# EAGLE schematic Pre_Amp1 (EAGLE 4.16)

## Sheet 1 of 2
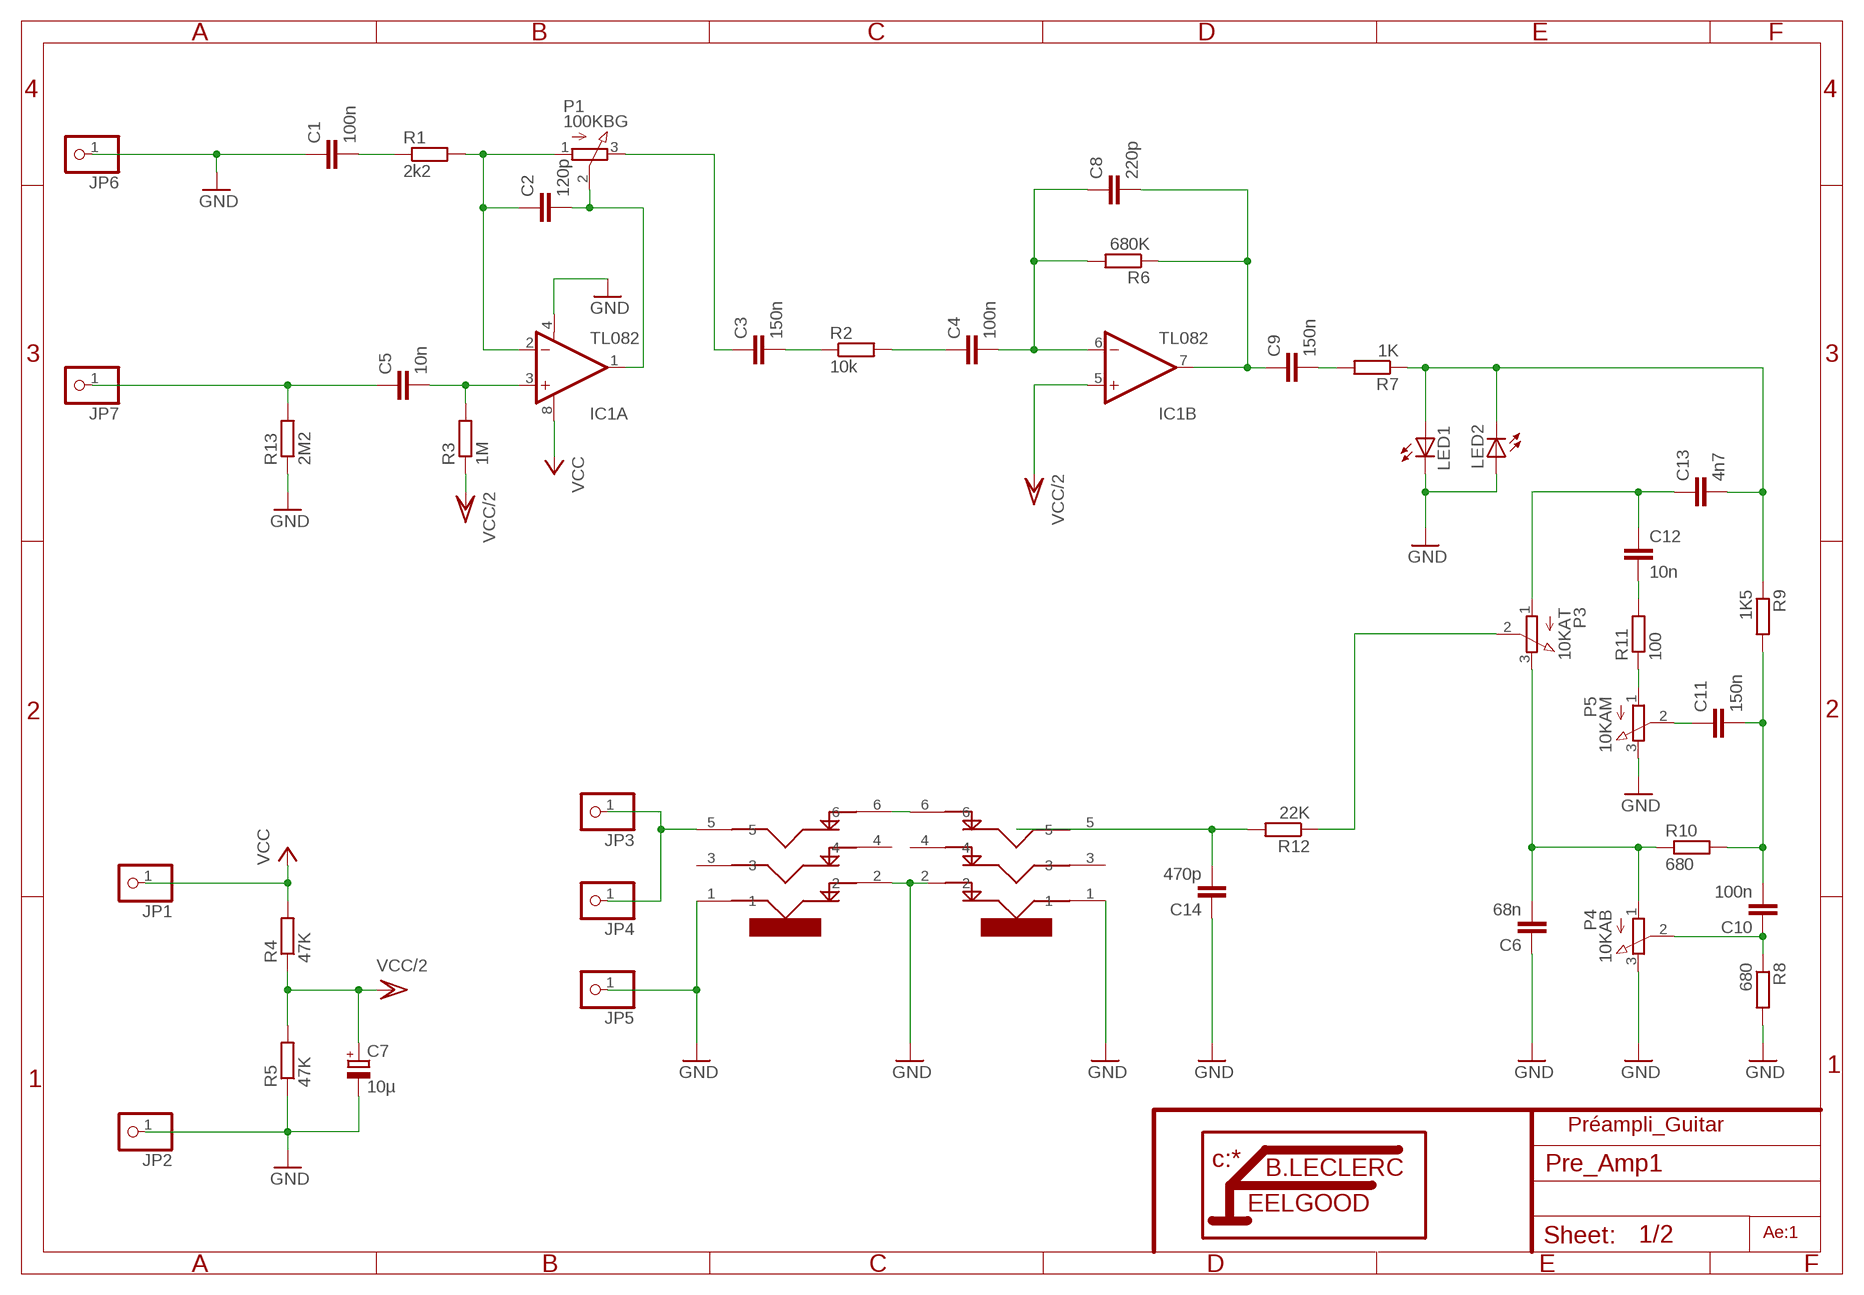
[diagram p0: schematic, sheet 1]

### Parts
C1  100n  C-EU102-043X133  [C102-043X133]
C2  120p  C-EU025-025X050  [C025-025X050]
C3  150n  C-EU102-054X133  [C102-054X133]
C4  100n  C-EU102-054X133  [C102-054X133]
C5  10n  C-EU050-035X075  [C050-035X075]
C6  68n  C-EU050-035X075  [C050-035X075]
C7  10µ  CPOL-EUE2.5-6  [E2,5-6]
C8  220p  C-EU050-030X075  [C050-030X075]
C9  150n  C-EU102-043X133  [C102-043X133]
C10  100n  C-EU102-043X133  [C102-043X133]
C11  150n  C-EU102-043X133  [C102-043X133]
C12  10n  C-EU050-025X075  [C050-025X075]
C13  4n7  C-EU050-025X075  [C050-025X075]
C14  470p  C-EU050-025X075  [C050-025X075]
IC1  TL082  OPA2134P  [DIL08]
J2  Return  JACK635  [JACK635]
J3  Send  JACK635  [JACK635]
JP1  PINHD-1X1  [1X01]
JP2  PINHD-1X1  [1X01]
JP3  PINHD-1X1  [1X01]
JP4  PINHD-1X1  [1X01]
JP5  PINHD-1X1  [1X01]
JP6  PINHD-1X1  [1X01]
JP7  PINHD-1X1  [1X01]
LED1  LED3MM  [LED3MM]
LED2  LED3MM  [LED3MM]
P1  100KBG  STD-EU  [STD-EU]
P3  10KAT  STD-EU  [STD-EU]
P4  10KAB  STD-EU  [STD-EU]
P5  10KAM  STD-EU  [STD-EU]
R1  2k2  R-EU_0207/10  [0207/10]
R2  10k  R-EU_0207/10  [0207/10]
R3  1M  R-EU_0207/10  [0207/10]
R4  47K  R-EU_0207/10  [0207/10]
R5  47K  R-EU_0207/10  [0207/10]
R6  680K  R-EU_0207/10  [0207/10]
R7  1K  R-EU_0207/10  [0207/10]
R8  680  R-EU_0207/10  [0207/10]
R9  1K5  R-EU_0207/10  [0207/10]
R10  680  R-EU_0207/10  [0207/10]
R11  100  R-EU_0207/10  [0207/10]
R12  22K  R-EU_0207/10  [0207/10]
R13  2M2  R-EU_0207/10  [0207/10]

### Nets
GND: C1.1 C6.1 C7.- C14.1 IC1.4(A:V-) J2.1 J2.2 J3.1 J3.2 JP2.1 JP5.1 JP6.1 LED1.K(C) LED2.A P4.3(E) P5.3(E) R5.1 R8.2 R13.1 ; also sheet 2
N$1: C1.2 R1.1
N$2: C2.1 IC1.2(A:-IN) P1.1(A) R1.2
N$3: C2.2 IC1.1(A:OUT) P1.2(S)
N$4: C10.1 P4.2(S) R8.1
N$5: C5.1 JP7.1 R13.2
N$6: C5.2 IC1.3(A:+IN) R3.2
N$7: C6.2 P3.3(E) P4.1(A) R10.1
N$8: C3.1 P1.3(E)
N$9: C3.2 R2.1
N$10: C4.1 R2.2
N$11: C4.2 C8.1 IC1.6(B:-IN) R6.2
N$13: C8.2 C9.1 IC1.7(B:OUT) R6.1
N$14: C9.2 R7.2
N$15: C13.2 LED1.A LED2.K(C) R7.1 R9.1
N$16: P3.2(S) R12.1
N$17: C12.1 C13.1 P3.1(A)
N$18: C12.2 R11.2
N$19: P5.1(A) R11.1
N$20: C11.1 P5.2(S)
N$21: C10.2 C11.2 R9.2 R10.2
N$23: C14.2 J3.5 R12.2
N$28: J2.6 J3.6
N$29: J2.5 JP3.1 JP4.1
VCC: IC1.8(A:V+) JP1.1 R4.2
VCC/2: C7.+ IC1.5(B:+IN) R3.1 R4.1 R5.2
Unconnected: J2.3 J2.4 J3.3 J3.4

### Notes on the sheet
- Préampli_Guitar
- Ae:1

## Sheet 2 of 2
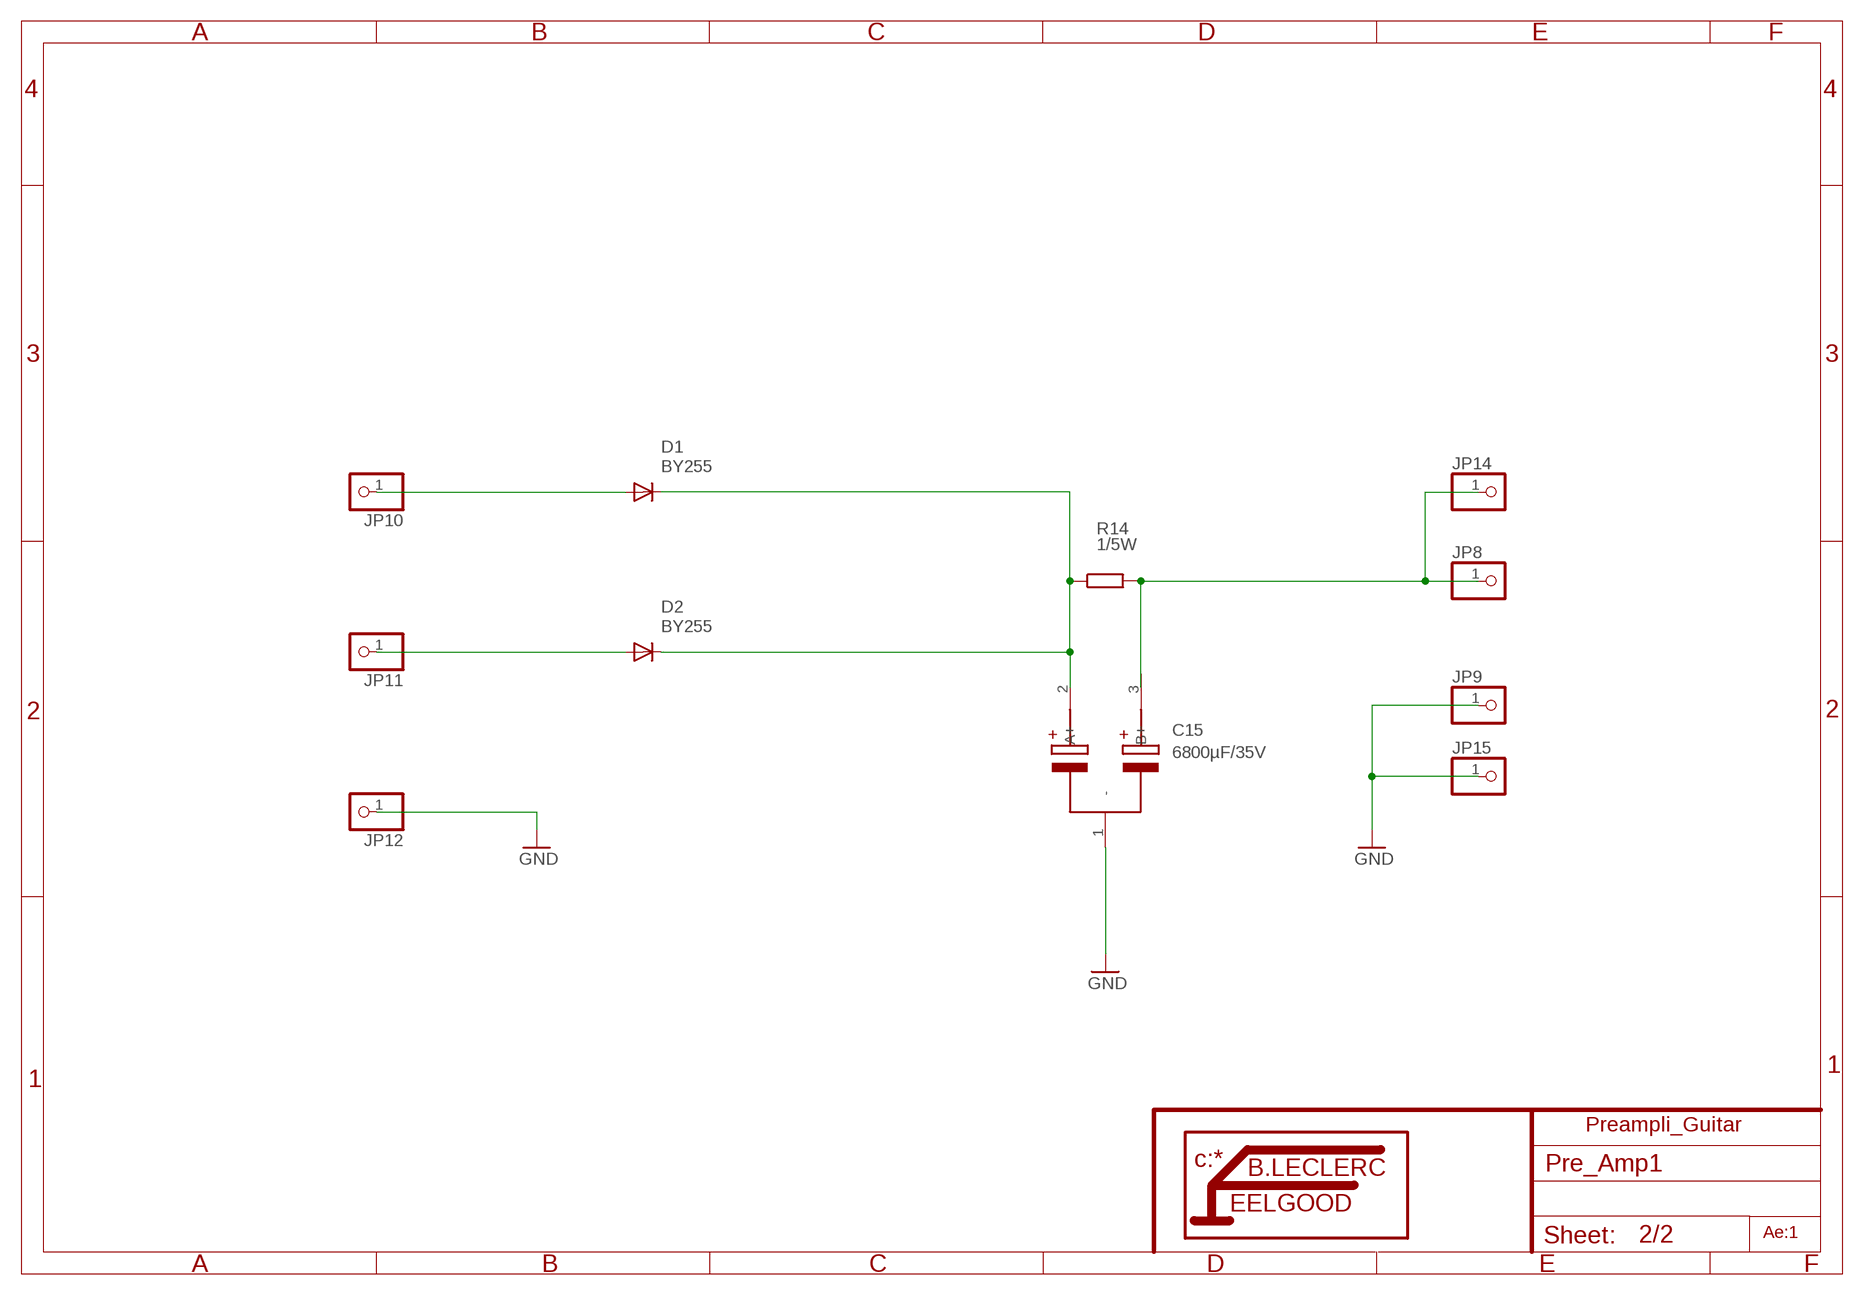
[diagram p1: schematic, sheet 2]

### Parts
C15  6800µF/35V  C-POL-X2  [C-POL-X2]
D1  BY255  DIODE-DO15-12  [DO15-12]
D2  BY255  DIODE-DO15-12  [DO15-12]
JP8  PINHD-1X1  [1X01]
JP9  PINHD-1X1  [1X01]
JP10  PINHD-1X1  [1X01]
JP11  PINHD-1X1  [1X01]
JP12  PINHD-1X1  [1X01]
JP14  PINHD-1X1  [1X01]
JP15  PINHD-1X1  [1X01]
R14  1/5W  R-EU_0414/15  [0414/15]

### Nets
GND: C15.1(-) JP9.1 JP12.1 JP15.1 ; also sheet 1
N$37: D1.A JP10.1
N$55: D2.A JP11.1
N$56: C15.2(A+) D1.C D2.C R14.1
N$77: C15.3(B+) JP14.1 R14.2
Unconnected: JP8.1

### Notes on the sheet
- Preampli_Guitar
- Ae:1

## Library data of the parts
C1-C6 C8-C14 = rcl:C-EU: CAPACITOR, European symbol
C7 = rcl:CPOL-EU: POLARIZED CAPACITOR, European symbol
C15 = rcl:C-POL-X2
D1 D2 = diode:DIODE-: DIODE
IC1 = burr-brown:OPA2134: Operational Amplifier
J2 J3 = Con-Audio:JACK635
JP1-JP12 JP14 JP15 = pinhead:PINHD-1X1: PIN HEADER
LED1 LED2 = led:LED: LED
P1 P3-P5 = pot:STD-EU
R1-R14 = rcl:R-EU_: RESISTOR, European symbol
